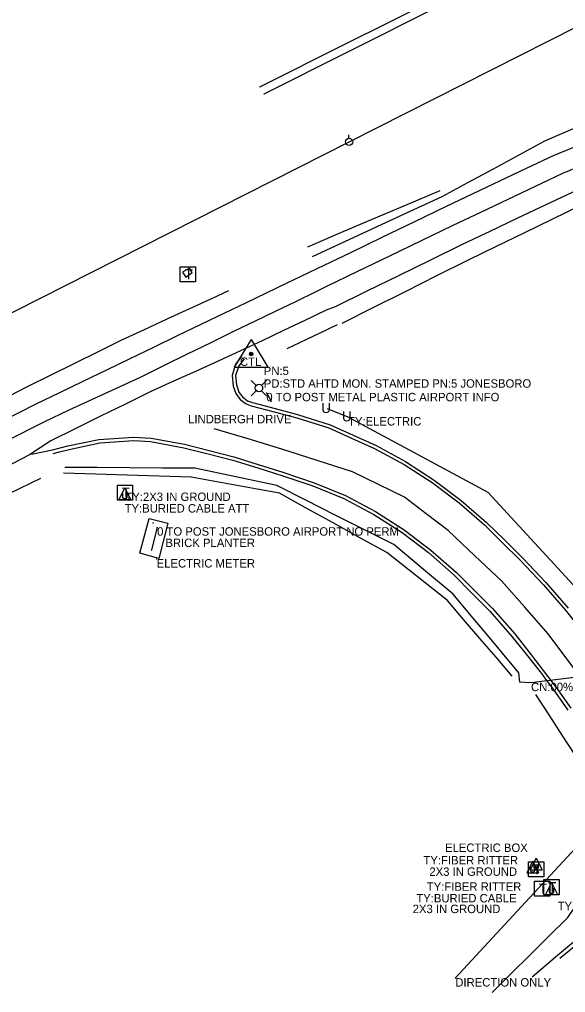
# Model space of a CAD drawing. Extents: x 1707085 to 1720058, y 548761 to 560063.
# Drawn here: x 1711331 to 1711655, y 548951 to 549528 of the extents above; entities that cross this region are included whole.
import ezdxf

# ---------------------------------------------------------------- set-up
doc = ezdxf.new("R2010")
doc.units = 0
for name, color, linetype in [('22', 7, 'Continuous'), ('3', 7, 'Continuous'), ('Default', 7, 'Continuous'), ('R_Contour Annot', 7, 'Continuous'), ('R_Horz Alg Annot', 7, 'Continuous'), ('S_CURB', 7, 'Continuous'), ('S_DRG_PT_SYM', 7, 'Continuous'), ('S_EDGE_CONCRETE', 7, 'Continuous'), ('S_EDGE_PAVEMENT', 7, 'Continuous'), ('S_MISC_STRUCTURES_ANNOT', 7, 'Continuous'), ('S_MSC_PT_SYM', 7, 'Continuous'), ('S_PAVEMENT_CROWN', 7, 'Continuous'), ('S_PRIMARY_CTL_ANNOT', 7, 'Continuous'), ('S_SANITARY_SEWER', 7, 'Continuous'), ('S_SANITARY_SEWER_ANNOT', 7, 'Continuous'), ('S_SIDE_DRAIN_ANNOT', 7, 'Continuous'), ('S_SIGN_ANNOT', 7, 'Continuous'), ('S_SURVEY_TEXT_ANNOT', 7, 'Continuous'), ('S_TELEPHONE_UTILITIES', 7, 'Continuous'), ('S_TELEPHONE_UTILITIES_ANNOT', 7, 'Continuous'), ('S_UNDERGROUND_CABLE', 7, 'Continuous'), ('S_UNDERGROUND_CABLE_ANNOT', 7, 'Continuous'), ('S_UTILITY_POLE', 7, 'Continuous'), ('S_UTILITY_POLE_ANNOT', 7, 'Continuous'), ('S_UTL_PT_SYM', 7, 'Continuous'), ('S_WALL', 7, 'Continuous')]:
    doc.layers.add(name, color=color, linetype=linetype)

msp = doc.modelspace()

# ---------------------------------------------------------------- linework, layer by layer
for points in [[(1711665.6, 549465.74), (1711642.7, 549455.95), (1711627.43, 549447.67), (1711612.16, 549439.38), (1711596.89, 549431.1), (1711581.62, 549422.81), (1711562.43, 549413.93), (1711543.24, 549405.04), (1711524.06, 549396.15), (1711504.87, 549387.27)], [(1711580.48, 549426.47), (1711560.88, 549418.12), (1711541.27, 549409.78), (1711521.67, 549401.43), (1711502.06, 549393.08)], [(1711663.48, 549417.49), (1711646.94, 549409.44), (1711630.41, 549401.39), (1711613.88, 549393.34), (1711597.34, 549385.29), (1711578.62, 549375.91), (1711559.89, 549366.53), (1711541.17, 549357.15), (1711522.44, 549347.77)], [(1711455.15, 549367.15), (1711445.42, 549362.61), (1711432.02, 549356.39), (1711418.62, 549350.17), (1711405.22, 549343.95), (1711391.82, 549337.73), (1711377.83, 549330.81), (1711363.84, 549323.9), (1711349.85, 549316.99), (1711335.86, 549310.07), (1711313.79, 549298.83)], [(1711519.62, 549346.94), (1711508.89, 549341.79), (1711489.72, 549332.6)], [(1711634.46, 549134.3), (1711628.03, 549134.85), (1711627.35, 549140.42), (1711617.63, 549152.06), (1711607.92, 549163.71), (1711598.2, 549175.35), (1711588.48, 549187), (1711570.88, 549201.72), (1711553.27, 549216.45), (1711535.9, 549225.23), (1711518.52, 549234.01), (1711501.15, 549242.79), (1711483.78, 549251.57), (1711459.52, 549256.67), (1711435.26, 549261.76), (1711415.96, 549261.89), (1711396.65, 549262.02), (1711377.35, 549262.14), (1711358.05, 549262.27)], [(1711343.75, 549255.71), (1711325, 549246.53)], [(1711623.46, 549138.37), (1711613.85, 549149.57), (1711604.25, 549160.78), (1711594.65, 549171.99), (1711585.04, 549183.2), (1711567.07, 549197.43), (1711549.11, 549211.66), (1711533.17, 549220.49), (1711517.23, 549229.31), (1711501.29, 549238.14), (1711485.36, 549246.97), (1711472.27, 549249.32), (1711459.17, 549251.68), (1711446.08, 549254.03), (1711432.99, 549256.39), (1711414.09, 549257), (1711395.19, 549257.6), (1711376.28, 549258.21), (1711357.38, 549258.82)], [(1711611.51, 548950.56), (1711622.73, 548961.7), (1711633.95, 548972.84), (1711645.16, 548983.98), (1711656.38, 548995.12), (1711665.63, 549008.46), (1711674.87, 549021.8), (1711673.4, 549036.12), (1711671.93, 549050.43), (1711670.45, 549064.75), (1711668.98, 549079.06), (1711661.08, 549091.17), (1711653.18, 549103.27), (1711645.28, 549115.38), (1711637.38, 549127.48)]]:
    msp.add_lwpolyline(points)
at = {"layer": '22'}
for p, q in [((1711577.67, 549540.23), (1711523.96, 549513.27)), ((1711579.84, 549535.89), (1711526.2, 549508.94)), ((1711523.96, 549513.27), (1711473.9, 549488.22)), ((1711526.2, 549508.94), (1711476.25, 549483.81))]:
    msp.add_line(p, q, dxfattribs=at)
at = {"layer": '3'}
msp.add_line((1711699.29, 549142.3), (1711634.65, 549134.46), dxfattribs=at)
at = {"layer": 'R_Contour Annot'}
for p, q in [((1711468.61, 549338.27), (1711458.57, 549321.75)), ((1711468.61, 549338.27), (1711478.43, 549321.75)), ((1711458.57, 549321.75), (1711478.43, 549321.75))]:
    msp.add_line(p, q, dxfattribs=at)
for radius in [1.04, 0.609, 0.344]:
    msp.add_circle((1711468.61, 549329.57), radius, dxfattribs=at)
at = {"layer": 'R_Horz Alg Annot'}
for p, q in [((1711477.65, 549306.49), (1711480.44, 549301.52)), ((1711412.86, 549226.74), (1711409.45, 549213.11))]:
    msp.add_line(p, q, dxfattribs=at)
at = {"layer": 'S_CURB'}
for points in [[(1711464.53, 549326.76), (1711461.31, 549322.63), (1711459.4, 549316.75), (1711459.86, 549311.27), (1711461.37, 549306.91), (1711463.54, 549304.2), (1711466.42, 549301.86), (1711469.36, 549300.75), (1711482.79, 549297.2), (1711496.21, 549293.64), (1711515.43, 549287.54), (1711529.07, 549281.36), (1711542.71, 549275.18), (1711560.18, 549265.67), (1711577.13, 549254.74), (1711593.17, 549242.65), (1711608.28, 549229.65), (1711619.02, 549219.02), (1711629.77, 549208.39), (1711643.49, 549193.99), (1711656.55, 549178.8)], [(1711351.22, 549270.53), (1711354.93, 549271.47), (1711360.65, 549272.96), (1711378.94, 549276.9), (1711399.05, 549278.14), (1711408.99, 549277.54), (1711428.62, 549273.81), (1711443.21, 549270.22), (1711457.79, 549266.63), (1711472.59, 549261.95), (1711487.39, 549257.27), (1711505.23, 549251.24), (1711523.62, 549243.86), (1711541.31, 549234.31), (1711558.21, 549223.6), (1711573.78, 549211.68), (1711588.98, 549198.32), (1711599.59, 549187.67), (1711610.19, 549177.02), (1711623.33, 549161.94), (1711631.66, 549151.42), (1711639.99, 549140.9), (1711641.8, 549138.53), (1711643.28, 549136.47), (1711645.26, 549133.99), (1711647.77, 549130.54), (1711656.35, 549118.18)], [(1711664.62, 548984.47), (1711650.28, 548972.62), (1711635.27, 548959.6)]]:
    msp.add_lwpolyline(points, dxfattribs=at)
at = {"layer": 'S_DRG_PT_SYM'}
msp.add_lwpolyline([(1711634.65, 549134.46), (1711634.65, 549134.51), (1711634.65, 549134.46), (1711634.6, 549134.46), (1711634.65, 549134.46), (1711634.65, 549134.41), (1711634.65, 549134.46), (1711634.7, 549134.46)], dxfattribs=at)
at = {"layer": 'S_EDGE_CONCRETE'}
msp.add_lwpolyline([(1711433.7, 549377.86), (1711432.08, 549380.48), (1711427.95, 549378.11), (1711429.87, 549375.11)], close=True, dxfattribs=at)
at = {"layer": 'S_EDGE_PAVEMENT'}
for points in [[(1711669.9, 549456.22), (1711647.71, 549447.1), (1711631.83, 549439.59), (1711615.96, 549432.09), (1711600.08, 549424.58), (1711584.2, 549417.07), (1711565.15, 549407.86), (1711546.11, 549398.65), (1711527.06, 549389.44), (1711508.01, 549380.23), (1711502.21, 549377.46), (1711489.88, 549371.57), (1711477.55, 549365.67), (1711465.23, 549359.77), (1711452.9, 549353.87), (1711438.86, 549347.07), (1711424.82, 549340.27), (1711410.78, 549333.47), (1711396.74, 549326.67), (1711382.78, 549319.95), (1711368.83, 549313.23), (1711354.88, 549306.5), (1711340.93, 549299.78), (1711318.65, 549288.53)], [(1711669.9, 549456.22), (1711647.71, 549447.1), (1711631.83, 549439.59), (1711615.96, 549432.09), (1711600.08, 549424.58), (1711584.2, 549417.07), (1711565.15, 549407.86), (1711546.11, 549398.65), (1711527.06, 549389.44), (1711508.01, 549380.23)], [(1711659.43, 549425.69), (1711643, 549417.91), (1711626.58, 549410.14), (1711610.15, 549402.37), (1711593.72, 549394.59), (1711574.9, 549385.33), (1711556.07, 549376.06), (1711537.25, 549366.79), (1711518.42, 549357.53), (1711513.11, 549355.58), (1711500.43, 549349.53), (1711487.76, 549343.48), (1711475.08, 549337.43), (1711462.41, 549331.37), (1711448.99, 549325.3), (1711435.58, 549319.23), (1711422.16, 549313.16), (1711408.74, 549307.08), (1711394.03, 549299.83), (1711379.31, 549292.58), (1711364.6, 549285.32), (1711349.89, 549278.07), (1711337.1, 549269.7), (1711318.38, 549260)], [(1711659.43, 549425.69), (1711643, 549417.91), (1711626.58, 549410.14), (1711610.15, 549402.37), (1711593.72, 549394.59), (1711574.9, 549385.33), (1711556.07, 549376.06), (1711537.25, 549366.79), (1711518.42, 549357.53)], [(1711462.95, 549328.11), (1711459.43, 549323.47), (1711457.39, 549316.84), (1711457.87, 549310.57), (1711459.56, 549306.05), (1711462.1, 549302.61), (1711465.76, 549299.93), (1711468.68, 549298.75), (1711482.21, 549295.23), (1711495.74, 549291.71), (1711514.68, 549285.73), (1711528.22, 549279.62), (1711541.75, 549273.5), (1711559.3, 549263.97), (1711575.98, 549253.32), (1711591.96, 549241.26), (1711606.97, 549228.16), (1711617.59, 549217.65), (1711628.21, 549207.13), (1711641.98, 549192.65), (1711655.07, 549177.46), (1711667.27, 549161.8)], [(1711338.36, 549270.05), (1711350.83, 549272.67), (1711360, 549274.98), (1711378.37, 549278.89), (1711398.86, 549280.13), (1711409.26, 549279.62), (1711429.05, 549275.98), (1711443.66, 549272.29), (1711458.27, 549268.6), (1711472.88, 549263.98), (1711487.49, 549259.36), (1711505.93, 549253.05), (1711524.63, 549245.6), (1711542.32, 549236.05), (1711559.33, 549225.29), (1711575.11, 549213.21), (1711590.37, 549199.89), (1711601.02, 549189.19), (1711611.67, 549178.49), (1711624.99, 549163.5), (1711634.73, 549150.92), (1711644.48, 549138.33), (1711649.62, 549131.57), (1711658.16, 549119.26)], [(1711663.4, 548980.29), (1711651.69, 548970.68)]]:
    msp.add_lwpolyline(points, dxfattribs=at)
at = {"layer": 'S_MSC_PT_SYM'}
for points in [[(1711523.96, 549513.27), (1711523.96, 549513.32), (1711523.96, 549513.27), (1711523.91, 549513.27), (1711523.96, 549513.27), (1711523.96, 549513.22), (1711523.96, 549513.27), (1711524.01, 549513.27)], [(1711526.2, 549508.94), (1711526.2, 549508.99), (1711526.2, 549508.94), (1711526.15, 549508.94), (1711526.2, 549508.94), (1711526.2, 549508.89), (1711526.2, 549508.94), (1711526.25, 549508.94)], [(1711473.9, 549488.22), (1711473.9, 549488.27), (1711473.9, 549488.22), (1711473.85, 549488.22), (1711473.9, 549488.22), (1711473.9, 549488.17), (1711473.9, 549488.22), (1711473.95, 549488.22)], [(1711476.25, 549483.81), (1711476.25, 549483.86), (1711476.25, 549483.81), (1711476.2, 549483.81), (1711476.25, 549483.81), (1711476.25, 549483.76), (1711476.25, 549483.81), (1711476.3, 549483.81)], [(1711477.65, 549306.49), (1711477.65, 549306.54), (1711477.65, 549306.49), (1711477.6, 549306.49), (1711477.65, 549306.49), (1711477.65, 549306.44), (1711477.65, 549306.49), (1711477.7, 549306.49)], [(1711480.44, 549301.52), (1711480.44, 549301.57), (1711480.44, 549301.52), (1711480.39, 549301.52), (1711480.44, 549301.52), (1711480.44, 549301.47), (1711480.44, 549301.52), (1711480.49, 549301.52)], [(1711431.28, 549293.44), (1711431.28, 549293.49), (1711431.28, 549293.44), (1711431.23, 549293.44), (1711431.28, 549293.44), (1711431.28, 549293.39), (1711431.28, 549293.44), (1711431.33, 549293.44)], [(1711410.46, 549229.28), (1711410.46, 549229.33), (1711410.46, 549229.28), (1711410.41, 549229.28), (1711410.46, 549229.28), (1711410.46, 549229.23), (1711410.46, 549229.28), (1711410.51, 549229.28)], [(1711412.86, 549226.74), (1711412.86, 549226.79), (1711412.86, 549226.74), (1711412.81, 549226.74), (1711412.86, 549226.74), (1711412.86, 549226.69), (1711412.86, 549226.74), (1711412.91, 549226.74)], [(1711409.45, 549213.11), (1711409.45, 549213.16), (1711409.45, 549213.11), (1711409.4, 549213.11), (1711409.45, 549213.11), (1711409.45, 549213.06), (1711409.45, 549213.11), (1711409.5, 549213.11)], [(1711412.61, 549207.83), (1711412.61, 549207.88), (1711412.61, 549207.83), (1711412.56, 549207.83), (1711412.61, 549207.83), (1711412.61, 549207.78), (1711412.61, 549207.83), (1711412.66, 549207.83)], [(1711642.11, 549019.35), (1711642.11, 549019.4), (1711642.11, 549019.35), (1711642.06, 549019.35), (1711642.11, 549019.35), (1711642.11, 549019.3), (1711642.11, 549019.35), (1711642.16, 549019.35)]]:
    msp.add_lwpolyline(points, dxfattribs=at)
at = {"layer": 'S_PAVEMENT_CROWN'}
for points in [[(1711674.98, 549445.65), (1711653.34, 549436.67), (1711637.08, 549428.97), (1711620.82, 549421.28), (1711604.57, 549413.58), (1711588.31, 549405.88), (1711569.46, 549396.77), (1711550.61, 549387.66), (1711531.75, 549378.55), (1711512.9, 549369.44), (1711506.97, 549366.41), (1711494.88, 549360.59), (1711482.79, 549354.76), (1711470.69, 549348.93), (1711458.6, 549343.1), (1711444.65, 549336.24), (1711430.69, 549329.39), (1711416.74, 549322.53), (1711402.78, 549315.67), (1711388.59, 549309.1), (1711374.4, 549302.52), (1711360.21, 549295.94), (1711346.03, 549289.36), (1711323.76, 549278.01)], [(1711674.98, 549445.65), (1711653.34, 549436.67), (1711637.08, 549428.97), (1711620.82, 549421.28), (1711604.57, 549413.58), (1711588.31, 549405.88), (1711569.46, 549396.77), (1711550.61, 549387.66), (1711531.75, 549378.55), (1711512.9, 549369.44)], [(1711667.36, 549133.3), (1711656.01, 549148.51), (1711644.65, 549163.71), (1711630.91, 549179.29), (1711617.17, 549194.86), (1711601.32, 549209.79), (1711585.47, 549224.73), (1711572.48, 549234.65), (1711559.48, 549244.56), (1711544.08, 549252.09), (1711528.67, 549259.63), (1711507.77, 549266.39), (1711486.86, 549273.16), (1711466.8, 549279.19), (1711446.73, 549285.22)]]:
    msp.add_lwpolyline(points, dxfattribs=at)
at = {"layer": 'S_SANITARY_SEWER'}
msp.add_line((1711671.61, 549047.9), (1711589.69, 548959.11), dxfattribs=at)
at = {"layer": 'S_TELEPHONE_UTILITIES'}
for points in [[(1711426.63, 549372.39), (1711426.63, 549381.39), (1711435.63, 549381.39), (1711435.63, 549372.39)], [(1711389.32, 549242.8), (1711389.32, 549251.8), (1711398.32, 549251.8), (1711398.32, 549242.8)], [(1711633.15, 549019.2), (1711633.15, 549028.2), (1711642.15, 549028.2), (1711642.15, 549019.2)], [(1711642.23, 549008.64), (1711642.23, 549017.64), (1711651.23, 549017.64), (1711651.23, 549008.64)], [(1711636.67, 549007.71), (1711636.67, 549016.71), (1711645.67, 549016.71), (1711645.67, 549007.71)]]:
    msp.add_lwpolyline(points, close=True, dxfattribs=at)
at = {"layer": 'S_UNDERGROUND_CABLE'}
for p, q in [((1711526.12, 549292.13), (1711513.82, 549297.08)), ((1711393.68, 549250.21), (1711390.15, 549243.12)), ((1711393.68, 549250.21), (1711397.17, 549243.12)), ((1711390.15, 549243.12), (1711397.17, 549243.12)), ((1711392.48, 549244.36), (1711392.48, 549246.8)), ((1711393.1, 549243.7), (1711392.48, 549244.36)), ((1711394.3, 549243.7), (1711393.1, 549243.7)), ((1711394.84, 549244.36), (1711394.3, 549243.7)), ((1711394.84, 549246.8), (1711394.84, 549244.36)), ((1711635.6, 549028.61), (1711632.08, 549021.52)), ((1711637.72, 549030.39), (1711634.2, 549023.3)), ((1711635.6, 549028.61), (1711639.09, 549021.52)), ((1711637.72, 549030.39), (1711641.21, 549023.3)), ((1711634.2, 549023.3), (1711641.21, 549023.3)), ((1711634.4, 549022.76), (1711634.4, 549025.2)), ((1711635.02, 549022.1), (1711634.4, 549022.76)), ((1711636.77, 549022.76), (1711636.22, 549022.1)), ((1711636.52, 549024.54), (1711636.52, 549026.98)), ((1711637.14, 549023.88), (1711636.52, 549024.54)), ((1711636.77, 549025.2), (1711636.77, 549022.76)), ((1711638.34, 549023.88), (1711637.14, 549023.88)), ((1711638.89, 549024.54), (1711638.34, 549023.88)), ((1711638.89, 549026.98), (1711638.89, 549024.54)), ((1711632.08, 549021.52), (1711639.09, 549021.52)), ((1711636.22, 549022.1), (1711635.02, 549022.1)), ((1711646.8, 549015.92), (1711643.27, 549008.83)), ((1711645.6, 549010.07), (1711645.6, 549012.51)), ((1711646.8, 549015.92), (1711650.29, 549008.83)), ((1711647.96, 549012.51), (1711647.96, 549010.07)), ((1711643.27, 549008.83), (1711650.29, 549008.83)), ((1711646.22, 549009.41), (1711645.6, 549010.07)), ((1711647.42, 549009.41), (1711646.22, 549009.41)), ((1711647.96, 549010.07), (1711647.42, 549009.41))]:
    msp.add_line(p, q, dxfattribs=at)
msp.add_lwpolyline([(1711661.93, 549190.04), (1711609.23, 549247.35), (1711526.12, 549292.13)], dxfattribs=at)
at = {"layer": 'S_UTILITY_POLE'}
for p, q in [((1711526.61, 549457.6), (1711526.61, 549459.71)), ((1711471.63, 549310.96), (1711468.64, 549313.94)), ((1711474.81, 549310.96), (1711477.79, 549313.94)), ((1711471.63, 549307.78), (1711468.64, 549304.8)), ((1711474.81, 549307.78), (1711477.79, 549304.8))]:
    msp.add_line(p, q, dxfattribs=at)
msp.add_lwpolyline([(1711064.39, 549251.72), (1711313.01, 549347.35), (1711526.73, 549455.46), (1711746.33, 549566.96), (1712411.7, 549904.79), (1712500.91, 549949.57)], dxfattribs=at)
for centre, radius in [((1711526.73, 549455.46), 2.13), ((1711473.23, 549309.38), 2.21)]:
    msp.add_circle(centre, radius, dxfattribs=at)
at = {"layer": 'S_UTL_PT_SYM'}
msp.add_lwpolyline([(1711589.69, 548959.11), (1711589.69, 548959.16), (1711589.69, 548959.11), (1711589.64, 548959.11), (1711589.69, 548959.11), (1711589.69, 548959.06), (1711589.69, 548959.11), (1711589.74, 548959.11)], dxfattribs=at)
at = {"layer": 'S_WALL'}
msp.add_lwpolyline([(1711419.21, 549229.2), (1711413.88, 549208.13), (1711402.68, 549211.27), (1711408.1, 549231.89)], close=True, dxfattribs=at)

# ---------------------------------------------------------------- texts
at = {"layer": 'Default'}
for p in [(1711510.19, 549294.53), (1711522.49, 549289.58)]:
    msp.add_text('U', height=6, rotation=360, dxfattribs=at).set_placement(p)
at = {"layer": 'R_Contour Annot'}
msp.add_text('CTL', height=5, rotation=360, dxfattribs=at).set_placement((1711462.02, 549322.49))
at = {"layer": 'S_MISC_STRUCTURES_ANNOT'}
for s, p in [('ELECTRIC METER', (1711412.61, 549202.83)), ('ELECTRIC BOX', (1711583.63, 549034.01))]:
    msp.add_text(s, height=5, dxfattribs=at).set_placement(p)
at = {"layer": 'S_PRIMARY_CTL_ANNOT'}
for s, p in [('PN:5', (1711476.11, 549317.07)), ('PD:STD AHTD MON. STAMPED PN:5 JONESBORO', (1711476.11, 549309.57))]:
    msp.add_text(s, height=5, dxfattribs=at).set_placement(p)
at = {"layer": 'S_SANITARY_SEWER_ANNOT'}
msp.add_text('DIRECTION ONLY', height=5, dxfattribs=at).set_placement((1711589.69, 548954.11))
at = {"layer": 'S_SIDE_DRAIN_ANNOT'}
msp.add_text('CN:00%FILL', height=5, dxfattribs=at).set_placement((1711634.65, 549129.46))
at = {"layer": 'S_SIGN_ANNOT'}
for s, p in [('0 TO POST METAL PLASTIC AIRPORT INFO', (1711477.65, 549301.49)), ('0 TO POST JONESBORO AIRPORT NO PERM', (1711412.86, 549221.74))]:
    msp.add_text(s, height=5, dxfattribs=at).set_placement(p)
at = {"layer": 'S_SURVEY_TEXT_ANNOT'}
for s, p in [('LINDBERGH DRIVE', (1711431.28, 549288.44)), ('BRICK PLANTER', (1711417.78, 549215))]:
    msp.add_text(s, height=5, dxfattribs=at).set_placement(p)
at = {"layer": 'S_TELEPHONE_UTILITIES'}
for p in [(1711429.19, 549373.89), (1711391.89, 549244.3), (1711635.71, 549020.7), (1711639.23, 549009.21), (1711644.79, 549010.14)]:
    msp.add_text('T', height=6, rotation=360, dxfattribs=at).set_placement(p)
at = {"layer": 'S_TELEPHONE_UTILITIES_ANNOT'}
for s, p in [('TY:2X3 IN GROUND', (1711394.05, 549242.32)), ('2X3 IN GROUND', (1711574.33, 549019.83)), ('2X3 IN GROUND', (1711564.43, 548997.71))]:
    msp.add_text(s, height=5, dxfattribs=at).set_placement(p)
at = {"layer": 'S_UNDERGROUND_CABLE_ANNOT'}
msp.add_text('TY:ELECTRIC', height=5, dxfattribs=at).set_placement((1711526.12, 549287.13))
at = {"layer": 'S_UTILITY_POLE_ANNOT'}
for s, p in [('TY:BURIED CABLE ATT', (1711393.61, 549235.47)), ('TY:FIBER RITTER', (1711570.85, 549026.61)), ('TY:FIBER RITTER', (1711572.79, 549010.96)), ('TY:BURIED CABLE', (1711566.59, 549004.06)), ('TY:CONC', (1711650.4, 548999.43))]:
    msp.add_text(s, height=5, dxfattribs=at).set_placement(p)

doc.saveas('drawing.dxf')
